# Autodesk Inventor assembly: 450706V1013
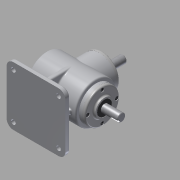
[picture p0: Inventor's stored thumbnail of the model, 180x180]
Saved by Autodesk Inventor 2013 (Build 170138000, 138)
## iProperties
Created: 2015-07
Part Number: 450706V1013
Document SubType Name: Assembly
Designer: Administrator
Author: Administrator
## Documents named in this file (14)
- C:\Users\Administrator\Desktop\450706V1013\450706V1013.iam
- C:\Users\Administrator\Desktop\450706V1013\본체 - 1.ipt
- C:\Users\Administrator\Desktop\450706V1013\커버.ipt
- C:\Users\Administrator\Desktop\450706V1013\오일실.ipt
- C:\Users\Administrator\Desktop\450706V1013\베어링 6203.ipt
- C:\Users\Administrator\Desktop\450706V1013\메인 축.ipt
- 메인 축.ipt
- C:\Users\Administrator\Desktop\450706V1013\키 5x5.ipt
- C:\Users\Administrator\Desktop\450706V1013\메인 베벨기어.ipt
- C:\Users\Administrator\Desktop\450706V1013\서브 축.ipt
- 서브 축.ipt
- C:\Users\Administrator\Desktop\450706V1013\키 4x4.ipt
- C:\Users\Administrator\Desktop\450706V1013\서브 베벨기어.ipt
- C:\Users\Administrator\Desktop\450706V1013\M4.ipt
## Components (8 placed, 1 different names)
1. M4:1
2. M4:3
3. M4:4
4. M4:5
5. M4:2
6. M4:6
7. M4:7
8. M4:8
